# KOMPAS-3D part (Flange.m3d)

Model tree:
1. Plane XY
2. Plane ZX
3. Plane ZY
4. X Axis
5. Y Axis
6. Z Axis
7. Origin
8. Sketch:1
9. Extrude:1
     Wall Thickness 1 = 1; Wall Thickness 2 = 1; Distance 1 = 40; Distance 2 = 10
10. Sketch:2
11. Cut-Extrude:1
     Wall Thickness 1 = 1; Wall Thickness 2 = 1; Distance 2 = 10; Distance 1 = 40
12. Circular Pattern:1  (with: Cut-Extrude:1)  (labels: Instance ( 1, 1 );; Instance ( 1, 2 );; Instance ( 1, 3 );; Instance ( 1, 4 );)
     N 1 = 1; Spacing 1 = 10; N 2 = 6; Spacing 2 = 360
13. Sketch:3
14. Cut-Extrude:2
     Wall Thickness 1 = 1; Wall Thickness 2 = 1; Distance 2 = 10; Distance 1 = 40

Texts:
  Steel DIN 17102
  Three Point Plane
  Plane at Angle
  Line and Point Plane
  Axis through Two Vertices
  Axis of Feature
  Axis of Conical Surface
  Axis through Edge
  Trim by Surface
  Trim by Sketch
  Feature with No History
  Intersection Axis of Two Planes
  Two Line Plane
  Line and Face Plane
  Bend by line
  Hole in sheet body
  Cut in sheet body
  Point in CM
  Linear Dimension from Line to Point
  Surface Finish Symbol
  Geometric Tolerance Symbol
  Bend by sketch
  Arc of Circle
  Junction of curves
  Array by nodes of sketch
  Leader #1
  Leader #2
  Leader #3
  Shape Deviations and Datum
  Node point number
  Mark of coordination axis
  Node point designation
  Mark/Reference designation with leader
  Mark/reference designation on line
  Mark/Reference designation without leader
  Flange_Diam-30
  Instance ( 1, 1 );
  Instance ( 1, 2 );
  Instance ( 1, 3 );
  Instance ( 1, 4 );
  Instance ( 1, 5 );
  Instance ( 1, 6 );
